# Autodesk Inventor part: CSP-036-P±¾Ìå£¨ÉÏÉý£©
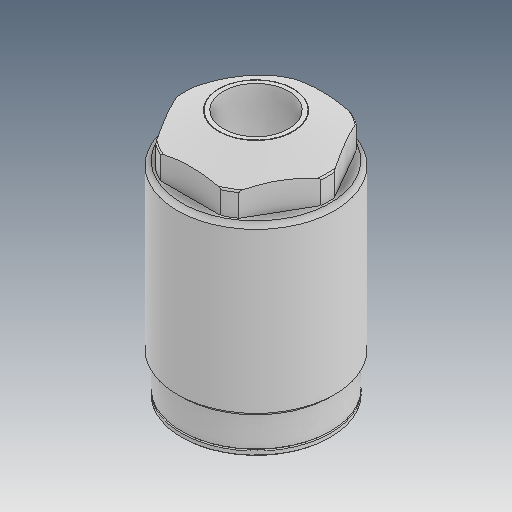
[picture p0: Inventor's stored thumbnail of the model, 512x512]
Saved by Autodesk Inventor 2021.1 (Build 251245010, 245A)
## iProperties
Created: 2019-01
Part Number: CSP-036-P±¾Ìå£¨ÉÏÉý£©
Material: Ogólny
Document SubType Name: Modeling
Designer: user
Density: 1 g/cm^3
Appearance: Domyślna
Author: user
Revision Number: ÈÎºÎ
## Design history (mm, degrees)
feature "ÇÐ³ý-À­Éì2"
node "Bryła1"
